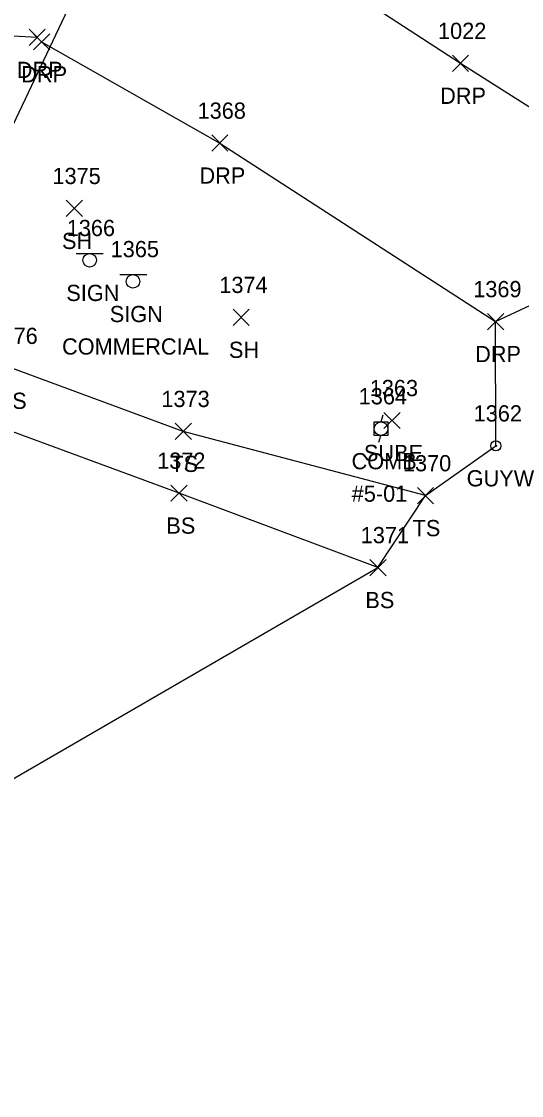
# Model space of a CAD drawing. Extents: x 1639430 to 1640195, y 612006 to 612917.
# Drawn here: x 1639782.3 to 1639843.9, y 612311.8 to 612444.1 of the extents above; entities that cross this region are included whole.
import ezdxf

# ---------------------------------------------------------------- set-up
doc = ezdxf.new("R2010")
doc.units = 0
for name, color, linetype in [('DCP', 7, 'Continuous'), ('L_A', 7, 'Continuous'), ('L_I', 7, 'Continuous'), ('L_TIC', 7, 'Continuous'), ('LELB', 7, 'Continuous'), ('LSOGP', 7, 'Continuous'), ('R_A', 7, 'Continuous'), ('R_I', 7, 'Continuous'), ('R_TIC', 7, 'Continuous'), ('RDP', 7, 'Continuous'), ('S_A', 7, 'Continuous'), ('S_C', 7, 'Continuous'), ('S_I', 7, 'Continuous'), ('SSGN', 7, 'Continuous'), ('U_A', 7, 'Continuous'), ('U_C', 7, 'Continuous'), ('U_I', 7, 'Continuous'), ('U_TIC', 7, 'Continuous'), ('UP', 7, 'Continuous'), ('UPGW', 7, 'Continuous')]:
    doc.layers.add(name, color=color, linetype=linetype)

msp = doc.modelspace()

# ---------------------------------------------------------------- linework, layer by layer
at = {"layer": 'DCP'}
msp.add_lwpolyline([(1639836.53, 612547.97), (1639769.19, 612405.95)], dxfattribs=at)
at = {"layer": 'L_TIC'}
for points in [[(1639787.82, 612420.09), (1639789.82, 612422.09)], [(1639789.82, 612420.09), (1639787.82, 612422.09)], [(1639808.38, 612406.67), (1639810.38, 612408.67)], [(1639810.38, 612406.67), (1639808.38, 612408.67)], [(1639801.24, 612392.62), (1639803.24, 612394.62)], [(1639803.24, 612392.62), (1639801.24, 612394.62)], [(1639800.72, 612385.01), (1639802.72, 612387.01)], [(1639802.72, 612385.01), (1639800.72, 612387.01)], [(1639831.09, 612384.7), (1639833.09, 612386.7)], [(1639833.09, 612384.7), (1639831.09, 612386.7)], [(1639825.23, 612375.84), (1639827.23, 612377.84)], [(1639827.23, 612375.84), (1639825.23, 612377.84)]]:
    msp.add_lwpolyline(points, dxfattribs=at)
at = {"layer": 'LELB'}
for points in [[(1639832.09, 612385.7), (1639802.24, 612393.62), (1639781.12, 612401.39), (1639773.28, 612407.77), (1639764.29, 612408.76), (1639762.78, 612398.94), (1639766.11, 612382.09), (1639764.88, 612355.41)], [(1639826.23, 612376.84), (1639801.72, 612386.01), (1639778.09, 612394.73), (1639771.95, 612397.87), (1639769.65, 612405.44), (1639769.55, 612405.43), (1639768.09, 612406.04), (1639766.54, 612399.08), (1639767.34, 612381.02), (1639767.53, 612353.97)]]:
    msp.add_lwpolyline(points, dxfattribs=at)
at = {"layer": 'LSOGP'}
msp.add_lwpolyline([(1639728.6, 612301.29), (1639735.53, 612313.13), (1639769.45, 612328.45), (1639770.43, 612331.76), (1639770.95, 612334.08), (1639773.74, 612342.38), (1639775.25, 612344.87), (1639777.85, 612348.84), (1639826.23, 612376.84), (1639832.09, 612385.7), (1639840.76, 612391.84), (1639840.72, 612407.15), (1639868.59, 612420.18)], dxfattribs=at)
at = {"layer": 'R_TIC'}
for points in [[(1639783.24, 612441.16), (1639785.24, 612443.16)], [(1639785.24, 612441.16), (1639783.24, 612443.16)], [(1639783.8, 612440.62), (1639785.8, 612442.62)], [(1639785.8, 612440.62), (1639783.8, 612442.62)], [(1639835.4, 612437.97), (1639837.4, 612439.97)], [(1639837.4, 612437.97), (1639835.4, 612439.97)], [(1639805.75, 612428.14), (1639807.75, 612430.14)], [(1639807.75, 612428.14), (1639805.75, 612430.14)], [(1639839.72, 612406.15), (1639841.72, 612408.15)], [(1639841.72, 612406.15), (1639839.72, 612408.15)]]:
    msp.add_lwpolyline(points, dxfattribs=at)
at = {"layer": 'RDP'}
for points in [[(1639791.07, 612492.27), (1639790.56, 612482.42), (1639792.35, 612472.77), (1639797.16, 612465.25), (1639817.68, 612451.17), (1639836.4, 612438.97), (1639858.15, 612425.17), (1639868.59, 612420.18), (1639882.11, 612420.19), (1639897.25, 612425.27), (1639908.83, 612433.43), (1639923.77, 612450.11), (1639940.54, 612474.05), (1639946.23, 612483.43), (1639977.68, 612473.21), (1640001.7, 612464.66), (1640045.39, 612450.23), (1640094.56, 612433.69), (1640113.57, 612427.07)], [(1639784.24, 612442.16), (1639773.89, 612442.71), (1639765.69, 612441.27), (1639757.28, 612435.5)], [(1639784.24, 612442.16), (1639784.8, 612441.62)], [(1639784.8, 612441.62), (1639806.75, 612429.14), (1639840.72, 612407.15)]]:
    msp.add_lwpolyline(points, dxfattribs=at)
at = {"layer": 'SSGN'}
for p, q in [((1639789.06, 612415.54), (1639792.39, 612415.54)), ((1639790.71, 612414.7), (1639790.71, 612414.7)), ((1639794.41, 612412.93), (1639797.74, 612412.93)), ((1639796.05, 612412.1), (1639796.05, 612412.1))]:
    msp.add_line(p, q, dxfattribs=at)
for centre in [(1639790.71, 612414.7), (1639796.05, 612412.1)]:
    msp.add_circle(centre, 0.833, dxfattribs=at)
at = {"layer": 'U_TIC'}
for points in [[(1639826.96, 612393.96), (1639828.96, 612395.96)], [(1639828.96, 612393.96), (1639826.96, 612395.96)]]:
    msp.add_lwpolyline(points, dxfattribs=at)
at = {"layer": 'UP'}
for p, q in [((1639825.76, 612393.12), (1639825.76, 612394.78)), ((1639825.76, 612394.78), (1639827.43, 612394.78)), ((1639826.85, 612395.62), (1639826.6, 612394.78)), ((1639827.43, 612394.78), (1639827.43, 612393.12)), ((1639826.6, 612393.95), (1639826.6, 612393.95)), ((1639827.43, 612393.12), (1639825.76, 612393.12)), ((1639826.35, 612392.28), (1639826.6, 612393.12))]:
    msp.add_line(p, q, dxfattribs=at)
msp.add_circle((1639826.6, 612393.95), 0.833, dxfattribs=at)
at = {"layer": 'UPGW'}
for radius in [0.625, 0.0833]:
    msp.add_circle((1639840.76, 612391.84), radius, dxfattribs=at)

# ---------------------------------------------------------------- texts
at = {"layer": 'L_A'}
for s, p in [('SH', (1639787.31, 612416.09)), ('SH', (1639807.87, 612402.67)), ('TS', (1639779.53, 612396.39)), ('TS', (1639800.65, 612388.62)), ('BS', (1639800.16, 612381.01)), ('TS', (1639830.5, 612380.7)), ('BS', (1639824.68, 612371.84))]:
    msp.add_text(s, height=2, dxfattribs=at).set_placement(p)
at = {"layer": 'L_I'}
for s, p in [('1375', (1639786.13, 612424.09)), ('1374', (1639806.69, 612410.67)), ('1376', (1639778.37, 612404.39)), ('1373', (1639799.55, 612396.62)), ('1372', (1639799.03, 612389.01)), ('1370', (1639829.31, 612388.7)), ('1371', (1639824.11, 612379.84))]:
    msp.add_text(s, height=2, dxfattribs=at).set_placement(p)
at = {"layer": 'R_A'}
for p in [(1639781.73, 612437.16), (1639782.29, 612436.62), (1639833.89, 612433.97), (1639804.24, 612424.14), (1639838.2, 612402.15)]:
    msp.add_text('DRP', height=2, dxfattribs=at).set_placement(p)
at = {"layer": 'R_I'}
for s, p in [('1022', (1639833.63, 612441.97)), ('1368', (1639804.01, 612432.14)), ('1369', (1639837.97, 612410.15))]:
    msp.add_text(s, height=2, dxfattribs=at).set_placement(p)
at = {"layer": 'S_A'}
for p in [(1639787.84, 612409.68), (1639793.19, 612407.08)]:
    msp.add_text('SIGN', height=2, dxfattribs=at).set_placement(p)
at = {"layer": 'S_C'}
msp.add_text('COMMERCIAL', height=2, dxfattribs=at).set_placement((1639787.31, 612403.08))
at = {"layer": 'S_I'}
for s, p in [('1366', (1639787.89, 612417.68)), ('1365', (1639793.3, 612415.08))]:
    msp.add_text(s, height=2, dxfattribs=at).set_placement(p)
at = {"layer": 'U_A'}
for s, p in [('SUBE', (1639824.5, 612389.96)), ('COMB', (1639822.98, 612388.95)), ('GUYW', (1639837.16, 612386.84))]:
    msp.add_text(s, height=2, dxfattribs=at).set_placement(p)
at = {"layer": 'U_C'}
msp.add_text('#5-01', height=2, dxfattribs=at).set_placement((1639823, 612384.95))
at = {"layer": 'U_I'}
for s, p in [('1363', (1639825.22, 612397.96)), ('1364', (1639823.86, 612396.95)), ('1362', (1639838.02, 612394.84))]:
    msp.add_text(s, height=2, dxfattribs=at).set_placement(p)

doc.saveas('drawing.dxf')
